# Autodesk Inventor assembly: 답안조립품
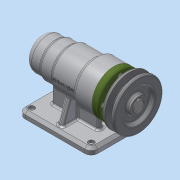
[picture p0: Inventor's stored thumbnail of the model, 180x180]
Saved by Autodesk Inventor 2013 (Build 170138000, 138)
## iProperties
Created: 2016-06
Part Number: 답안조립품
Document SubType Name: Assembly
Designer: dgall
Author: dgall
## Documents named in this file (12)
- C:\Users\dgall\Desktop\460607V1023\답안조립품.iam
- C:\Users\dgall\Desktop\460607V1023\본체.ipt
- C:\Users\dgall\Desktop\460607V1023\베어링 6004.ipt
- C:\Users\dgall\Desktop\460607V1023\축.ipt
- C:\Users\dgall\Desktop\460607V1023\커버.ipt
- C:\Users\dgall\Desktop\460607V1023\오일 실.ipt
- C:\Users\dgall\Desktop\460607V1023\키 5 x 5 x 16.ipt
- C:\Users\dgall\Desktop\460607V1023\V벨트풀리.ipt
- C:\Users\dgall\Desktop\460607V1023\멈춤나사 M3x8.ipt
- C:\Users\dgall\Desktop\460607V1023\어댑터슬리브.ipt
- C:\Users\dgall\Desktop\460607V1023\베어링 51202.ipt
- C:\Users\dgall\Desktop\460607V1023\볼트 M4 x 12.ipt
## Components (6 placed, 2 different names)
1. V벨트풀리:1
2. ISO 4762 M4 x 12:1
3. ISO 4762 M4 x 12:2
4. ISO 4762 M4 x 12:3
5. ISO 4762 M4 x 12:4
6. ISO 4762 M4 x 12:5
